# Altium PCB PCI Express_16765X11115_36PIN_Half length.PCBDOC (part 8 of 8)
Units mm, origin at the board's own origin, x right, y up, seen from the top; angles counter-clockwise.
Board outline 178 x 110.97 mm, 10 copper layers (Top Layer, Int1 (GND), Int2 (Sign), Int3 (Sign), Int4 (PWR), Int5 (GND), Int6 (Sign), Int7 (Sign), Int8 (GND), Bottom Layer), stack 1.429 mm thick; 528 components, 525 nets, 2272 pads, 1491 vias.
Unrouted connection lines stored in the file: 373.
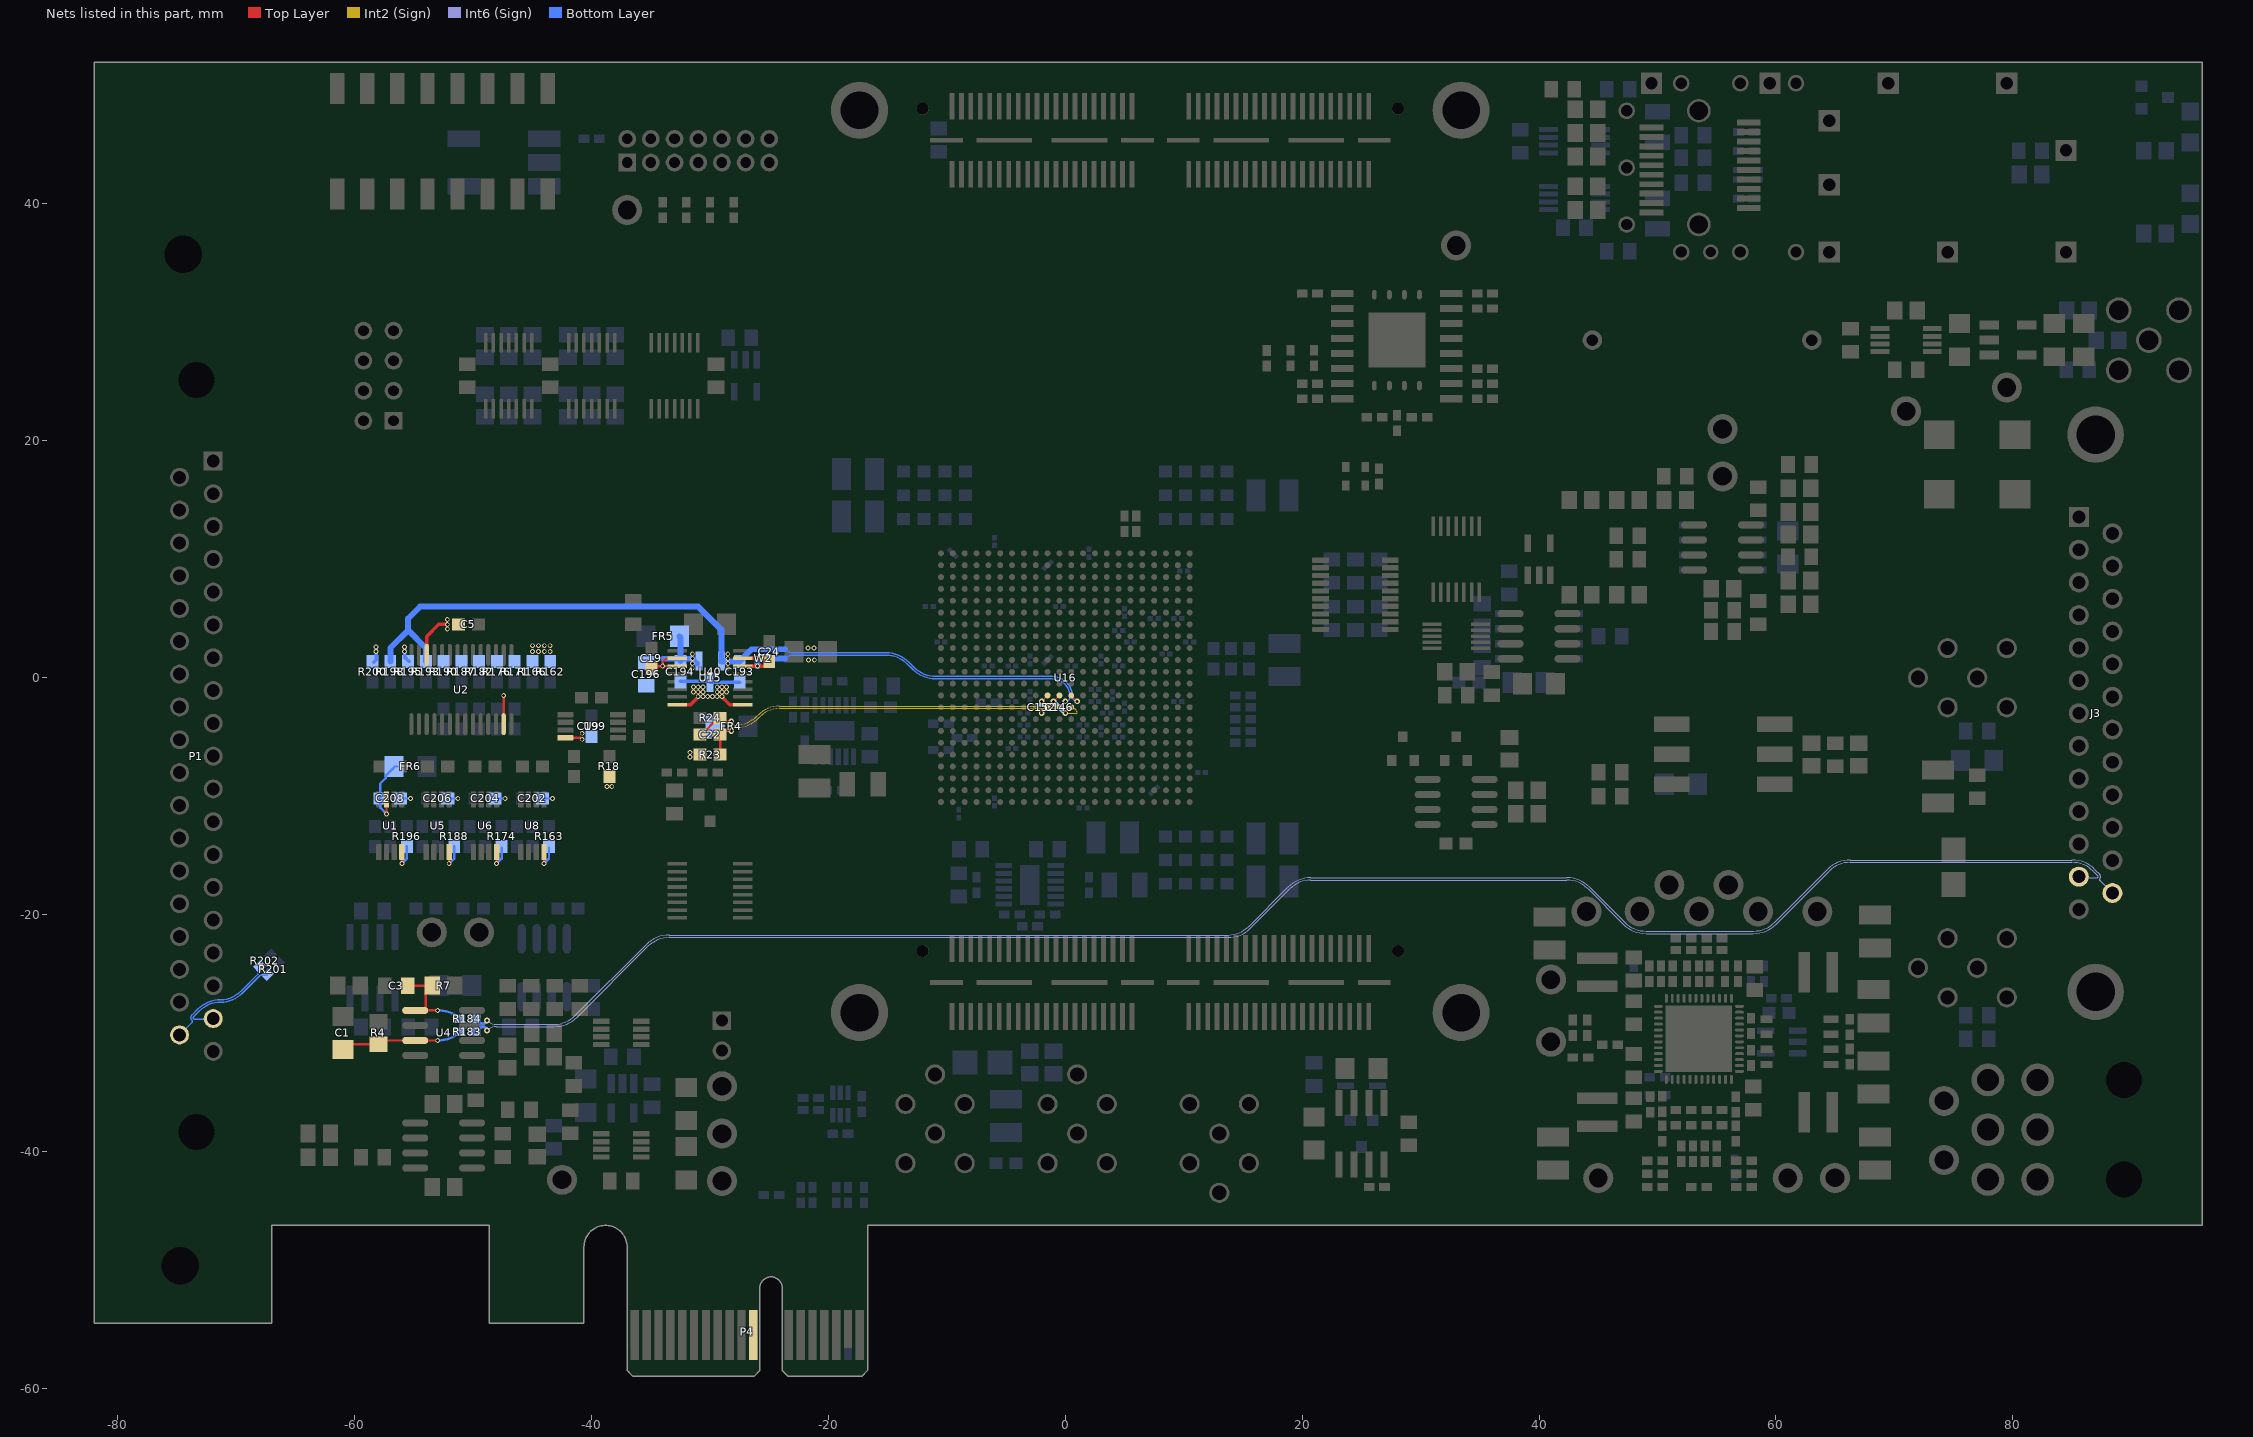
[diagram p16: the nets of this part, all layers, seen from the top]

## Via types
v1: diameter 0.483, hole 0.254, Top Layer to Bottom Layer, tented both sides, 740 vias
v2: diameter 0.508, hole 0.254, Top Layer to Bottom Layer, tented both sides, 302 vias
v3: diameter 0.406, hole 0.254, Top Layer to Bottom Layer, tented both sides, 267 vias
v4: diameter 0.305, hole 0.152, Top Layer to Bottom Layer, tented both sides, 95 vias
v5: diameter 0.5, hole 0.254, Top Layer to Bottom Layer, tented both sides, 50 vias
v6: diameter 0.45, hole 0.254, Top Layer to Bottom Layer, tented both sides, 23 vias
v7: diameter 0.6, hole 0.254, Top Layer to Bottom Layer, tented both sides, 14 vias

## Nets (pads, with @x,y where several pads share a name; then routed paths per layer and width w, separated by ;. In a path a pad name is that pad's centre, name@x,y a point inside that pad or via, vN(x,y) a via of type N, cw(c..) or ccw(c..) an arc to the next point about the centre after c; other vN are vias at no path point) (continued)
VREG2: C208.1 FR6.2 U1.7 | length 6.2
  Top Layer w0.203: v3(-57.325,-11.5) U1.7@-57.325,-10.275
  Bottom Layer w0.203: v3(-57.325,-11.5) -57.85,-10.975 C208.1@-57.85,-10.2 -57.85,-8.95 -57.398,-8.498 -57.398,-8.298 -56.6,-7.5 FR6.2@-56.4,-7.5
WAKE#: P4.B11
X1_N: P1.37 R202.2 | length 9.7
  Bottom Layer w0.127: P1.37@-74.795,-30.17 -73.75,-29.125 ccw(c-73.84,-29.035) -73.713,-29.035 ccw(c-73.84,-29.035) -73.75,-28.945 ; -73.751,-28.944 cw(c-73.519,-28.713) -73.846,-28.713 -73.846,-28.71 cw(c-73.52,-28.71) -73.751,-28.479 -73.271,-28 cw(c-71.333,-29.937) -71.333,-27.197 ccw(c-71.333,-24.8) -69.639,-26.495 -68.17,-25.027 ccw(c-68.322,-24.875) -68.107,-24.875 ccw(c-68.147,-24.875) -68.119,-24.847 cw(c-68.091,-24.819) -68.13,-24.819 -68.13,-24.53 cw(c-67.889,-24.53) R202.2@-68.06,-24.36
X1_P: P1.18 R201.2 | length 9.4
  Bottom Layer w0.127: P1.18@-71.955,-28.785 cw(c-72.084,-28.656) -72.084,-28.839 -73.516,-28.839 cw(c-73.516,-28.712) -73.606,-28.801 cw(c-73.516,-28.712) -73.643,-28.712 cw(c-73.516,-28.712) -73.606,-28.622 -73.128,-28.144 cw(c-71.332,-29.94) -71.332,-27.4 -71.33,-27.4 ccw(c-71.33,-24.808) -69.497,-26.641 -68.027,-25.17 cw(c-67.875,-25.322) -67.875,-25.107 cw(c-67.875,-25.147) -67.847,-25.119 ccw(c-67.819,-25.091) -67.819,-25.13 -67.53,-25.13 ccw(c-67.53,-24.889) R201.2@-67.36,-25.06
XADC.XADC_REF_N: U16.L9 W2.2 | length 28.4
  Top Layer w0.127: U16.L9@-0.5,-2.5 v1(0,-2)
  Bottom Layer w0.127: -23.66,1.63 cw(c-23.009,0.979) -23.009,1.9 -15.139,1.9 cw(c-15.139,-0.64) -13.343,1.156 -12.89,0.703 ccw(c-10.952,2.642) -10.952,-0.1 -10.651,-0.1 ; -10.65,-0.1 -1.103,-0.1 cw(c-1.103,-1.602) 0.398,-1.602 cw(c0,-1.602) v1(0,-2)
  Bottom Layer w0.5: W2.2@-25.162,1.63 -23.66,1.63
XADC.XADC_REF_P: C193.1 R193.2 R198.2 U16.M10 U40.2 | length 71.1
  Top Layer w0.127: U16.M10@0.5,-1.5 v1(1,-2)
  Bottom Layer w0.127: -23.657,2.4 -23.614,2.358 ccw(c-23,2.972) -23,2.103 -15.137,2.103 cw(c-15.137,-0.634) -13.202,1.302 -12.747,0.847 ccw(c-10.951,2.643) -10.951,0.103 -10.651,0.103 -1.103,0.103 cw(c-1.103,-1.602) 0.602,-1.599 cw(c-1.103,-1.602) 0.602,-1.602 ccw(c1,-1.602) v1(1,-2)
  Bottom Layer w0.381: C193.1@-27.5,1.35 C193.1@-27.5,1.4
  Bottom Layer w0.5: R198.2@-57,1.35 -57,2.5 -55.5,4 ; R193.2@-54,1.35 -54,2.5 -55.5,4 ; U40.2@-29.05,1.4 U40.2@-29.05,1.45 ; C193.1@-27.5,1.35 -28.5,1.35 -29.05,1.35 -29.1,1.4 U40.2@-29.05,1.45 ; C193.1@-27.5,1.4 -26.5,2.4 -23.657,2.4 ; -55.5,4 -55.5,5 -54.5,6 -53.3,6 -31,6 -29.05,4.05 U40.2@-29.05,1.45
  other v3: -28.5,0.8 -28.5,1.2 -28.5,1.6 -28.5,2
XADC.XADC_V_N: C22.2 C146.2 R23.2 U16.M9 | length 34.5
  Top Layer w0.127: v1(0,-3) U16.M9@0.5,-2.5
  Top Layer w0.203: R23.2@-29.15,-6.5 C22.2@-29.15,-4.8 -28.85,-4.5 v1(-28.2,-4.5)
  Int2 (Sign) w0.076: v1(-28.2,-4.5) cw(c-27.9,-4.5) -27.9,-4.2 -27.835,-4.2 ccw(c-27.835,-1.46) -25.897,-3.397 -25.8,-3.3 cw(c-24.11,-4.99) -24.11,-2.6 0.6,-2.6 cw(c0.6,-3) 1,-3 v1(0,-3)
XADC.XADC_V_P: C22.1 C146.1 R24.2 U16.L10 | length 32.1
  Top Layer w0.127: v1(-1,-2) U16.L10@-0.5,-1.5
  Top Layer w0.203: C22.1@-30.85,-4.8 -30.452,-4.402 -30.302,-4.402 -29.698,-3.798 -29.548,-3.798 R24.2@-29.15,-3.4 -28.85,-3.7 v1(-28.2,-3.7)
  Int2 (Sign) w0.076: v1(-28.2,-3.7) ccw(c-27.9,-3.7) -27.9,-4 -27.835,-4 ccw(c-27.835,-1.46) -26.039,-3.256 -25.941,-3.159 cw(c-24.11,-4.99) -24.11,-2.4 -1.4,-2.4 ccw(c-1.4,-2) v1(-1,-2)
XADCGND: C5.2 C19.1 C24.1 C152.1 C193.2 C194.2 C196.2 C199.2 C202.2 C204.2 C206.2 C208.2 FR4.2 R18.2 R23.1 R162.2 R163.2 R166.2 R171.2 R174.2 R176.2 R182.2 R187.2 R188.2 R190.2 R195.2 R196.2 R200.2 U1.4 U2.12 U2.27 U5.4 U6.4 U8.4 U9.4 U15.2 U15.3 U15.8 U15.9 U15.14 U15.15 U16.K9 U40.3 W2.1 | length 43.5
  Top Layer w0.127: v1(-2,-3) U16.K9@-1.5,-2.5
  Top Layer w0.203: v3@-56.025,-15.8 U1.4@-56.025,-14.725 ; v3@-52.026,-15.8 v3(-52.025,-15.7) U5.4@-52.025,-14.725 ; v3(-48.025,-15.7) U6.4@-48.025,-14.725 ; U2.27@-47.425,-3.925 v3(-47.425,-1.5) ; U8.4@-44.025,-14.725 -44.022,-14.728 v3(-44.022,-15.7) ; U9.4@-42.225,-5.075 -40.98,-5.075 -40.855,-5.2 v3(-40.8,-5.2) ; C19.1@-34.95,0.775 -34.75,0.975 v3(-34,0.975) ; U15.3@-32.775,0.975 v3(-34,0.975) ; U15.2@-32.775,1.625 -32.806,1.594 -33.743,1.594 -34,1.337 v3(-34,0.975)
  Top Layer w0.3: U2.12@-53.925,1.925 -53.925,3.475 -52.9,4.5 v3@-52.2,4.5 ; U15.8@-32.775,-2.275 -31.65,-2.275 -31,-1.625 v3(-31,-1.6) ; v3(-29,-1.6) -28.325,-2.275 U15.9@-27.225,-2.275 ; U15.14@-27.225,0.975 v3(-26,0.975) -25.35,0.975 C24.1@-25,1.325 ; U15.15@-27.225,1.625 -25.3,1.625 C24.1@-25,1.325 ; C24.1@-25,1.353 C24.1@-25,1.325
  Bottom Layer w0.203: C208.2@-56.1,-10.2 v3(-55.3,-10.2) ; v3(-56.025,-15.7) -55.6,-15.275 R196.2@-55.6,-14.25 ; C206.2@-52.2,-10.2 C206.2@-52.15,-10.2 v3(-51.3,-10.2) ; v3@-52.025,-15.7 -51.6,-15.274 R188.2@-51.6,-14.25 ; C204.2@-48.2,-10.2 C204.2@-48.15,-10.2 v3(-47.3,-10.2) ; v3(-48.025,-15.7) -47.6,-15.275 R174.2@-47.6,-14.35 ; C202.2@-44.2,-10.2 C202.2@-44.15,-10.2 v3(-43.3,-10.2) ; v3(-44.022,-15.7) -43.6,-15.277 R163.2@-43.6,-14.35
  Bottom Layer w0.3: R200.2@-58.4,1.3 -58.2,1.5 v3(-58.2,2.2) v3(-58.2,2.6) ; v3(-55.8,2.6) v3(-55.8,2.2) -55.8,1.75 -55.45,1.4 R195.2@-55.4,1.4 ; C194.2@-32.5,-0.3 -30.1,-0.3 U40.3@-30,-0.4 C193.2@-27.5,-0.4
  Bottom Layer w0.5: v3(-26,0.975) v3(-26,1.625)
  other v3: -38.7,-9.2 -38.3,-9.2 -31.7,-6.7 -31.7,-6.3 -40.8,-4.7 -30.6,-1.6 -30.2,-1.6 -29.8,-1.6 -29.4,-1.6 -31.4,-1.2 -31,-1.2 -30.6,-1.2 -29.4,-1.2 -29,-1.2 -28.6,-1.2 -31.4,-0.8 -31,-0.8 -30.6,-0.8 -29.4,-0.8 -29,-0.8 -28.6,-0.8 -45,2.2 -44.5,2.2 -44,2.2 -43.5,2.2 -21.731,2.5 -21.231,2.5 -45,2.7 -44.5,2.7 -44,2.7 -43.5,2.7 -52.189,4.1 -52.189,4.5 -52.189,4.9
XADCVCC: C152.2 C194.1 C196.1 FR5.2 U16.K10 U40.1 | length 5.9
  Top Layer w0.127: v1(-2,-2) U16.K10@-1.5,-1.5
  Bottom Layer w0.5: -34,1.6 C194.1@-32.5,1.6 ; FR5.2@-32.6,3.5 -32.5,3.4 C194.1@-32.5,1.6 ; C194.1@-32.5,1.4 C194.1@-32.5,1.6 ; U40.1@-31.1,1.2 v3(-31.5,1.6) C194.1@-32.5,1.6
  other v3: -31.5,0.8 -31.5,1.2 -21.7,1.5 -21.2,1.5 -31.5,2
XOCTR_N: C3.2 R7.2 R184.1 U4.5 | length 8.7
  Top Layer w0.203: C3.2@-55.8,-25.9 -55.7,-26 R7.2@-53.45,-26 -53.998,-26.548 -53.998,-27.886 U4.5@-54.21,-28.098 ; U4.5@-54.9,-28.095 -54.898,-28.098 U4.5@-54.21,-28.098 ; v3(-53,-28.1) -53.003,-28.098 U4.5@-54.21,-28.098
  Bottom Layer w0.203: v3(-53,-28.1) -52.84,-28.1 cw(c-52.84,-30.49) R184.1@-51.15,-28.8
XOCTR_P: C1.1 R4.2 R183.1 U4.7 | length 10
  Top Layer w0.203: C1.1@-60.7,-31.5 -60.7,-31.448 -60.202,-30.95 R4.2@-58,-30.95 ; R4.2@-57.9,-30.8 -57.735,-30.635 U4.7@-54.9,-30.635 v3(-53,-30.635)
  Bottom Layer w0.203: v3(-53,-30.635) -52.924,-30.635 ccw(c-52.924,-28.126) R183.1@-51.15,-29.9
XOCTRL_N: J3.25 R184.2 | length 148.7
  Int6 (Sign) w0.076: v2(-48.841,-28.933) ccw(c-48.044,-28.136) -48.044,-29.263 -43.164,-29.263 ccw(c-43.164,-26.723) -41.368,-28.519 -35.385,-22.536 cw(c-33.45,-24.472) -33.45,-21.735 13.713,-21.735 ccw(c13.713,-19.195) 15.509,-20.991 18.8,-17.7 cw(c20.738,-19.637) 20.738,-16.897 42.349,-16.897 cw(c42.349,-19.638) 44.287,-17.7 47.243,-20.656 ccw(c49.039,-18.86) 49.039,-21.4 58.098,-21.4 ccw(c58.098,-18.86) 59.894,-20.656 64.35,-16.2 cw(c66.288,-18.137) 66.288,-15.397 84.999,-15.397 cw(c84.999,-18.138) 86.937,-16.2 87.34,-16.603 cw(c87.145,-16.798) 87.421,-16.798 ; 87.421,-16.8 cw(c87.142,-16.8) 87.339,-16.997 ccw(c87.393,-17.051) 87.317,-17.051 ccw(c87.393,-17.051) 87.339,-17.105 J3.25@88.42,-18.186
  Bottom Layer w0.203: R184.2@-49.85,-28.8 cw(c-49.85,-29.041) -49.679,-28.871 -49.517,-29.033 cw(c-49.553,-29.07) -49.502,-29.07 ccw(c-49.45,-29.07) -49.486,-29.106 ccw(c-49.236,-28.856) -49.236,-29.21 -49.143,-29.21 ccw(c-49.143,-28.95) -48.959,-29.134 -48.941,-29.116 cw(c-48.8,-29.257) -48.8,-29.058 v2(-48.841,-28.933)
XOCTRL_P: J3.12 R183.2 | length 148.2
  Int6 (Sign) w0.076: v2(-48.841,-29.797) cw(c-48.044,-30.594) -48.044,-29.467 -43.163,-29.467 ccw(c-43.163,-26.726) -41.225,-28.664 -35.243,-22.682 cw(c-33.447,-24.478) -33.447,-21.938 13.714,-21.938 ccw(c13.714,-19.197) 15.652,-21.135 18.943,-17.844 cw(c20.739,-19.64) 20.739,-17.1 42.348,-17.1 cw(c42.348,-19.64) 44.144,-17.844 47.1,-20.8 ccw(c49.039,-18.861) 49.039,-21.603 58.099,-21.603 ccw(c58.099,-18.863) 60.037,-20.8 64.493,-16.344 cw(c66.289,-18.14) 66.289,-15.6 84.998,-15.6 cw(c84.998,-18.14) 86.794,-16.344 87.196,-16.746 cw(c87.142,-16.8) 87.218,-16.8 cw(c87.142,-16.8) 87.196,-16.854 cw(c87.142,-16.8) 87.142,-16.876 85.751,-16.876 cw(c85.751,-16.634) J3.12@85.58,-16.805
  Bottom Layer w0.203: R183.2@-49.85,-29.9 ccw(c-49.85,-29.659) -49.679,-29.829 -49.517,-29.667 ccw(c-49.553,-29.63) -49.502,-29.63 cw(c-49.45,-29.63) -49.486,-29.594 cw(c-49.236,-29.844) -49.236,-29.49 -49.143,-29.49 cw(c-49.143,-29.75) -48.959,-29.566 -48.941,-29.584 ccw(c-48.8,-29.443) -48.8,-29.642 v2(-48.841,-29.797)
pads on no net: J1.7 J1.23 J1.24 J2.MH1 J2.MH2 J3.26 J3.27 P1.S1 P1.S2 P3.12 P3.14 P4.B12 P5.1 P5.2 P5.3 P5.4 P5.89 P5.90 P6.89 P6.90 S2.2 S2.4 U2.2 U2.3 U2.13 U3.1 U3.5 U3.8 U16.A6 U16.AA9 U16.AA10 U16.AA11 U16.AA13 U16.AA14 U16.AA15 U16.AA16 U16.AB10 U16.AB11 U16.AB12 U16.AB13 U16.AB15 U16.AB16 U16.AB17 U16.B6 U16.C5 U16.C7 U16.D5 U16.D7 U16.E10 U16.F10 U16.T14 U16.T15 U16.T16 U16.U15 U16.U16 U16.V10 U16.V13 U16.V14 U16.V15 U16.W10 U16.W11 U16.W12 U16.W14 U16.W15 U16.W16 U16.Y11 U16.Y12 U16.Y13 U16.Y14 U16.Y16 U16.Y17 U18.4 U18.5 U18.6 U18.11 U18.12 U18.13 U18.14 U19.1 U19.6 U20.9 U23.6 U23.8 U27.2 U29.1 U31.1 U31.3 U31.5 U31.7 U31.8 U32.1 U33.1 U33.4 U42.1 U42.3 U42.5 U42.7 U42.8
copper on no net:
  other v3: -40.2,-9.2 -39.8,-9.2
  other v5: 26,26.5 27,26.5 28,26.5 29,26.5 30,26.5 26,27.5 27,27.5 28,27.5 29,27.5 30,27.5 26,28.5 27,28.5 28,28.5 29,28.5 30,28.5 26,29.5 27,29.5 28,29.5 29,29.5 30,29.5 26,30.5 27,30.5 28,30.5 29,30.5 30,30.5

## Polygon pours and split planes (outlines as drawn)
P12V on Int3 (Sign) "P12V_L04_P049" (solid, pour order 49): -61.5,-41.8 -61.5,-19 -41.857,-19 -32.357,-28.5 7,-28.5 7,-43.2 -37.585,-43.154 -42.6,-43.2 -44.2,-41.8
SFP_SH on Int3 (Sign) "S0" (solid, pour order 8): 95.5,34.5 46.5,34.5 46.5,51.5 95.5,51.5
no net on Int3 (Sign) "SHLD" (solid, pour order 4): -82,52 -77.5,52 -77.5,-54.5 -82,-54.5
NetC61_2 on Top Layer "NETC61_2_L01_P024" (solid, pour order 24): 63.375,-30.428 58.45,-30.428 58.45,-29.375 57.5,-29.375 57.5,-28.625 57.5,-28.3 59.375,-28.3 59.375,-22.248 63.375,-22.248
no net on Top Layer "NONET_L01_P083" (solid, pour order 83): -26.2,-5
GND on Top Layer "SW_GND" (solid, pour order 13): 66.8,-29.5 63.925,-29.5 63.925,-30.75 66.8,-30.75 66.8,-32 63.925,-32 63.925,-33.3 70.05,-33.3 70.05,-28.2 66.8,-28.2
NetC60_2 on Top Layer "SW_PWR_2" (solid, pour order 22): 63.2,-39.25 59.5,-39.25 59.5,-33.25 57.552,-33.25 57.552,-32.125 58.5,-32.125 58.5,-31.05 63.2,-31.05
GND on Top Layer "GND_L01_P077" (solid, pour order 77): 49.5,9 50,9.5 50,12.5 49.5,13 47.9,13 47.9,9
VCC on Top Layer "VCC_L01_P071" (solid, pour order 71): 38.702,12.103 38.702,10.048 ccw(c39.05,10.048) 39.05,9.7 40,9.7 ccw(c40,10) 40.3,10 40.3,11.8 ccw(c40,11.8) 40,12.1 38.7,12.1
no net on Top Layer "NONET_L01_P064" (solid, pour order 64): 57.6,12.6
no net on Top Layer "NONET_L01_P063" (solid, pour order 63): 57.4,12.6
P10V on Top Layer "P10V_L01_P055" (solid, pour order 55): 40.5,1.9 40.5,1.2 38.9,1.2 38.3,0.6 35.3,0.6 35.3,1.5 35.9,1.5 36.3,1.9
no net on Top Layer "NONET_L01_P056" (solid, pour order 56): 37.2,0
XADCVCC on Bottom Layer "XADCVCC_L10_P090" (solid, pour order 90): -2.4,-1.9 -2.4,-1.3 ccw(c-2.9,-1.3) -2.9,-0.8 -10.993,-0.8 cw(c-10.993,3.08) -13.736,0.336 ccw(c-15.58,-1.507) -15.58,1.1 -22.1,1.1 cw(c-22.1,1.5) -22.5,1.506 ccw(c-35.131,1.702) -22.5,1.9 -22.44,1.9 -15.066,1.9 cw(c-15.065,-0.431) -13.417,1.217 -12.895,0.695 ccw(c-10.976,2.614) -10.976,-0.1 -1.183,-0.1 cw(c-1.183,-1.748) -0.017,-0.583 cw(c-1.024,-1.59) 0.4,-1.59 0.4,-1.9 cw(c0,-1.9) 0,-2.3 -2,-2.3 cw(c-2,-1.9)
XADCGND on Bottom Layer "XADCGND_L10_P087" (solid, pour order 87): -2.8,-3.1 -2.8,-4.3 ccw(c-2.4,-4.3) -2.4,-4.7 -0.041,-4.7 ccw(c-0.041,-3.875) 0.543,-4.458 1.589,-3.41 ccw(c0.594,-2.417) 2,-2.417 2,0.1 ccw(c1.498,0.1) 1.498,0.602 -9.702,0.602 -10.529,0.602 cw(c-10.529,2.723) -12.222,1.445 ccw(c-15.058,-0.693) -13.712,2.594 ccw(c-15.268,-1.185) -15.273,2.902 -22.098,2.902 ccw(c-22.099,2.5) -22.5,2.5 -22.5,2.032 -14.868,2.035 cw(c-14.866,-0.213) -13.277,1.377 -12.683,0.784 ccw(c-11.032,2.436) -11.032,0.1 -1.099,0.1 cw(c-1.098,-1.598) 0.599,-1.598 0.599,-1.901 cw(c-0.198,-1.901) -0.198,-2.698 -2.398,-2.698 ccw(c-2.398,-3.1)
no net on Bottom Layer "NONET_L10_P086" (solid, pour order 86): -0.5,-1.5
no net on Bottom Layer "NONET_L10_P085" (solid, pour order 85): -24,3
GND on Bottom Layer "GND_L10_P084" (solid, pour order 84): 21.8,10.6 25,13.8 30.5,13.8 30.5,9 28,9 28,10.3 21.8,10.3
GND on Bottom Layer "GND_L10_P082" (solid, pour order 82): 7.9,17.5 7.9,17.9 9,19 9.2,19 9.2,17.5
no net on Bottom Layer "NONET_L10_P081" (solid, pour order 81): -10.7,19.2
no net on Bottom Layer "NONET_L10_P080" (solid, pour order 80): -20.5,14.8
AGND on Bottom Layer "AGND_L10_P076" (solid, pour order 76): 57,9.4 55.9,8.3 55.9,6.9 58.8,4 60.5,4 61.9,5.4 61.9,10.4 60.1,10.4 59.1,9.4
AGND on Bottom Layer "AGND_L10_P074" (solid, pour order 74): 45.6,4.2 45.4,4.4 43.5,4.4 43.5,2.6 45.4,2.6 45.6,2.8
P10V on Bottom Layer "P10V_L10_P073" (solid, pour order 73): 39.5,15 39.24,15 ccw(c39.24,12.46) 36.7,12.46 36.7,8.4 38.3,8.4 38.3,12.3 cw(c39.5,12.3) 39.5,13.5
P10V on Bottom Layer "P10V_L10_P068" (solid, pour order 68): 56.5,15 ccw(c56.5,14.5) 56,14.5 56,11.8 ccw(c56.5,11.8) 56.5,11.3 61.5,11.3 ccw(c61.5,11.8) 62,11.8 62,14.5 ccw(c61.5,14.5) 61.5,15
no net on Bottom Layer "NONET_L10_P067" (solid, pour order 67): 56.5,15
AGND on Bottom Layer "AGND_L10_P062" (solid, pour order 62): 32.7,4 ccw(c33,4) 33,3.7 33.5,3.7 ccw(c33.5,4) 33.8,4 33.8,5.2 cw(c34.2,5.2) 34.2,5.6 36,5.6 36,6.9 34.4,6.9 ccw(c34.4,5.2) 32.7,5.2
AGND on Bottom Layer "AGND_L10_P057" (solid, pour order 57): 41.3,0.5 41.3,-1.3 39.9,-2.7 37.3,-2.7 37.3,-1.6 39.4,-1.6 39.7,-1.3 39.7,0.5
P10V on Bottom Layer "NONET_L10_P054" (solid, pour order 54): 38.5,-1.3 38.5,0.796 38.904,1.2 40.5,1.2 40.5,1.899 36.299,1.899 35.9,1.5 34.4,1.5 34.4,-0.9 34.8,-1.3
GND on Bottom Layer "GND_L10_P053" (solid, pour order 53): -22.3,-3.2 -22.3,-3.7 -23.4,-4.8 -23.4,-5.8 -21.5,-5.8 -20.5,-4.8 -20.5,-3.7 -21.3,-3.7 -21.8,-3.2
no net on Bottom Layer "NONET_L10_P047" (solid, pour order 47): -41.2,-39.2
no net on Bottom Layer "NONET_L10_P046" (solid, pour order 46): -39.6,-33.1
no net on Bottom Layer "NONET_L10_P045" (solid, pour order 45): -42,-29.8
NetC128_2 on Bottom Layer "NETC88_2" (solid, pour order 44): 4.5,-19 4.5,-16 3.5,-15 3.5,-12 1.648,-12 1.648,-17.3 2.3,-17.3 2.7,-17.7 2.7,-19
no net on Bottom Overlay "NONET_L-01_P-001" (solid): -37.9,-39.5
AVCC1V8 on Int7 (Sign) "AVCC1V8_L08_P079" (solid, pour order 79): 42.5,-30.6 42.5,-35.2 -7.1,-35.2 -38.8,-3.5 -38.8,4.5 -34.5,4.5 -34.5,-1.7 -5.6,-30.6
no net on Int7 (Sign) "NONET_L08_P078" (solid, pour order 78): 43,-29
P5V on Int7 (Sign) "P5V_L08_P052" (solid, pour order 52): -66.748,-45.743 -66.748,-25.604 -60.296,-19.152 -41.704,-19.152 -34.252,-26.604 -34.252,-43.389 -36.606,-45.743 -40.849,-45.743 -48.455,-45.743
N12V on Int2 (Sign) "N12V_L03_P048" (solid, pour order 48): 12.198,-43.2 12.198,-28.52 -32.38,-28.52 -41.9,-19 -61.5,-19 -61.5,-41.8 -44.2,-41.8 -42.8,-43.2 -31.3,-43.2
GND on Int1 (GND) (split plane): 159 vertices, not listed, extent -81.49,-58.49 79.248,51.458
VREF2V5 on Int1 (GND) (split plane): -38.252,-43.748 -54.748,-43.748 -54.748,-25.252 -38.252,-25.252
VCC2 on Int1 (GND) (split plane): -33.252,5.396 -33.252,4.104 -36.178,1.178 -36.218,1.126 -36.244,1.065 -36.252,1 -36.252,0 -36.252,-6.5 -36.252,-9.396 -39.104,-12.248 -40,-12.248 -57.896,-12.248 -60.648,-9.496 -60.648,1.496 -55.896,6.248 -34.104,6.248
EXT12V on Int1 (GND) (split plane): 83.748,-33.104 83.748,-42.5 83.748,-42.896 82.796,-43.848 80.154,-43.848 72.752,-36.446 72.752,-27.104 74.104,-25.752 76.396,-25.752
12V on Int1 (GND) (split plane): 95.49,-45.74 -4.748,-45.74 -4.748,-36.604 -3.322,-35.178 -1.896,-33.752 39.5,-33.752 39.565,-33.744 39.626,-33.718 39.678,-33.678 39.718,-33.626 39.744,-33.565 39.752,-33.5 39.752,-25 39.745,-24.943 39.744,-24.935 39.733,-24.91 39.718,-24.874 39.709,-24.862 39.678,-24.822 32.678,-17.822 29.252,-14.396 29.252,-12.104 30.604,-10.752 64,-10.752 64.065,-10.744 64.126,-10.718 64.178,-10.678 67.678,-7.178 68.178,-6.678 79.678,4.822 79.696,4.844 79.718,4.874 79.744,4.935 79.752,5 79.752,6.5 79.752,24.6 79.744,24.665 79.718,24.726 79.678,24.778 61.778,42.678 61.726,42.718 61.665,42.744 61.6,42.752 24.604,42.752 20.252,47.104 20.252,51.458 95.49,51.458
XADCVCC on Int1 (GND) (split plane): -20.752,0.252 -35.748,0.252 -35.748,0.896 -32.896,3.748 -20.752,3.748
VCC1V8 on Int1 (GND) (split plane): 19.748,-2 19.748,-3.396 6.396,-16.748 4.604,-16.748 0.752,-12.896 0.752,-1.5 0.744,-1.435 0.718,-1.374 0.678,-1.322 0.626,-1.282 0.565,-1.256 0.5,-1.248 -11,-1.248 -11.065,-1.256 -11.126,-1.282 -11.178,-1.322 -13.678,-3.822 -13.718,-3.874 -13.744,-3.935 -13.752,-4 -13.752,-8.896 -14.604,-9.748 -16.748,-9.748 -16.748,-1.604 -12.896,2.248 19.748,2.248
VCC on Int4 (PWR) (split plane): 95.49,-45.74 -16.7,-45.74 -16.8,-45.749 -16.895,-45.778 -16.984,-45.826 -17.061,-45.889 -17.124,-45.966 -17.172,-46.055 -17.201,-46.15 -17.21,-46.25 -17.21,-58.289 -17.411,-58.49 -23.189,-58.49 -23.39,-58.289 -23.39,-51.55 -23.39,-51.546 -23.399,-51.386 -23.426,-51.225 -23.472,-51.068 -23.534,-50.916 -23.614,-50.773 -23.708,-50.64 -23.817,-50.517 -23.94,-50.408 -24.073,-50.314 -24.216,-50.234 -24.368,-50.172 -24.525,-50.126 -24.686,-50.099 -24.85,-50.09 -25.014,-50.099 -25.175,-50.126 -25.332,-50.172 -25.484,-50.234 -25.627,-50.314 -25.76,-50.408 -25.883,-50.517 -25.992,-50.64 -26.086,-50.773 -26.166,-50.916 -26.228,-51.068 -26.274,-51.225 -26.301,-51.386 -26.31,-51.546 -26.31,-51.55 -26.31,-58.289 -26.511,-58.49 -36.289,-58.49 -36.49,-58.289 -36.49,-48.075 -36.49,-48.071 -36.499,-47.871 -36.525,-47.669 -36.569,-47.471 -36.631,-47.276 -36.709,-47.088 -36.803,-46.907 -36.912,-46.736 -37.036,-46.574 -37.174,-46.424 -37.324,-46.286 -37.486,-46.162 -37.657,-46.053 -37.838,-45.959 -38.026,-45.881 -38.221,-45.819 -38.419,-45.775 -38.621,-45.749 -38.825,-45.74 -39.029,-45.749 -39.231,-45.775 -39.429,-45.819 -39.624,-45.881 -39.812,-45.959 -39.993,-46.053 -40.164,-46.162 -40.326,-46.286 -40.476,-46.424 -40.614,-46.574 -40.738,-46.736 -40.847,-46.907 -40.941,-47.088 -41.019,-47.276 -41.081,-47.471 -41.125,-47.669 -41.151,-47.871 -41.16,-48.071 -41.16,-48.075 -41.16,-53.99 -48.14,-53.99 -48.14,-46.25 -48.149,-46.15 -48.178,-46.055 -48.226,-45.966 -48.289,-45.889 -48.366,-45.826 -48.455,-45.778 -48.55,-45.749 -48.65,-45.74 -67,-45.74 -67.1,-45.749 -67.195,-45.778 -67.284,-45.826 -67.361,-45.889 -67.424,-45.966 -67.472,-46.055 -67.501,-46.15 -67.51,-46.25 -67.51,-53.99 -81.49,-53.99 -81.49,51.458 95.49,51.458
AVTT on Int4 (PWR) (split plane): -9.752,-3.5 -9.744,-3.565 -9.718,-3.626 -9.678,-3.678 -9.626,-3.718 -9.565,-3.744 -9.5,-3.752 -8.752,-3.752 -8.752,-8.5 -8.752,-20.748 -24.748,-20.748 -24.748,-0.752 -9.752,-0.752
AVCC on Int4 (PWR) (split plane): -4.752,1 -4.752,-0.5 -4.752,-4.5 -4.752,-5.5 -4.752,-6.5 -4.752,-20.748 -8.248,-20.748 -8.248,-8.5 -8.248,-3.5 -8.256,-3.435 -8.282,-3.374 -8.322,-3.322 -8.374,-3.282 -8.435,-3.256 -8.5,-3.248 -9.248,-3.248 -9.248,-0.5 -9.256,-0.435 -9.282,-0.374 -9.322,-0.322 -9.374,-0.282 -9.435,-0.256 -9.5,-0.248 -24.748,-0.248 -24.748,13.248 -4.752,13.248
VCCINT on Int4 (PWR) (split plane): 2.248,-1.5 2.256,-1.565 2.282,-1.626 2.322,-1.678 2.374,-1.718 2.435,-1.744 2.5,-1.752 16.896,-1.752 20.322,-5.178 34.748,-19.604 34.748,-21.3 34.756,-21.365 34.782,-21.426 34.822,-21.478 40.322,-26.978 40.374,-27.018 40.435,-27.044 40.5,-27.052 51.696,-27.052 65.622,-40.978 66.348,-41.704 66.348,-42.796 65.822,-43.322 65.596,-43.548 64.404,-43.548 60.851,-39.995 60.844,-39.935 60.818,-39.874 60.778,-39.822 60.726,-39.782 60.665,-39.756 60.605,-39.749 50.678,-29.822 50.626,-29.782 50.565,-29.756 50.5,-29.748 38.104,-29.748 29.178,-20.822 29.126,-20.782 29.065,-20.756 29,-20.748 -4.248,-20.748 -4.248,-5.5 -4.248,-4.5 -4.248,-0.752 2.248,-0.752
P10V on Int4 (PWR) (split plane): 38.248,10.096 38.248,4 38.256,3.935 38.282,3.874 38.322,3.822 40.448,1.696 40.448,1.504 39.596,0.652 37.004,0.652 36.752,0.904 36.752,10.096 37.004,10.348 37.996,10.348
VCC1V8 on Int4 (PWR) (split plane): 24.822,-0.178 34.422,-9.778 42.548,-17.904 42.548,-26.548 40.604,-26.548 35.252,-21.196 35.252,-19.5 35.244,-19.435 35.218,-19.374 35.178,-19.322 20.678,-4.822 17.178,-1.322 17.126,-1.282 17.065,-1.256 17,-1.248 2.752,-1.248 2.752,-0.5 2.744,-0.435 2.718,-0.374 2.678,-0.322 2.626,-0.282 2.565,-0.256 2.5,-0.248 -4.248,-0.248 -4.248,13.248 11.396,13.248
GND on Int5 (GND) (split plane): 95.49,-45.74 -16.7,-45.74 -16.8,-45.749 -16.895,-45.778 -16.984,-45.826 -17.061,-45.889 -17.124,-45.966 -17.172,-46.055 -17.201,-46.15 -17.21,-46.25 -17.21,-58.289 -17.411,-58.49 -23.189,-58.49 -23.39,-58.289 -23.39,-51.55 -23.39,-51.546 -23.399,-51.386 -23.426,-51.225 -23.472,-51.068 -23.534,-50.916 -23.614,-50.773 -23.708,-50.64 -23.817,-50.517 -23.94,-50.408 -24.073,-50.314 -24.216,-50.234 -24.368,-50.172 -24.525,-50.126 -24.686,-50.099 -24.85,-50.09 -25.014,-50.099 -25.175,-50.126 -25.332,-50.172 -25.484,-50.234 -25.627,-50.314 -25.76,-50.408 -25.883,-50.517 -25.992,-50.64 -26.086,-50.773 -26.166,-50.916 -26.228,-51.068 -26.274,-51.225 -26.301,-51.386 -26.31,-51.546 -26.31,-51.55 -26.31,-58.289 -26.511,-58.49 -36.289,-58.49 -36.49,-58.289 -36.49,-48.075 -36.49,-48.071 -36.499,-47.871 -36.525,-47.669 -36.569,-47.471 -36.631,-47.276 -36.709,-47.088 -36.803,-46.907 -36.912,-46.736 -37.036,-46.574 -37.174,-46.424 -37.324,-46.286 -37.486,-46.162 -37.657,-46.053 -37.838,-45.959 -38.026,-45.881 -38.221,-45.819 -38.419,-45.775 -38.621,-45.749 -38.825,-45.74 -39.029,-45.749 -39.231,-45.775 -39.429,-45.819 -39.624,-45.881 -39.812,-45.959 -39.993,-46.053 -40.164,-46.162 -40.326,-46.286 -40.476,-46.424 -40.614,-46.574 -40.738,-46.736 -40.847,-46.907 -40.941,-47.088 -41.019,-47.276 -41.081,-47.471 -41.125,-47.669 -41.151,-47.871 -41.16,-48.071 -41.16,-48.075 -41.16,-53.99 -48.14,-53.99 -48.14,-46.25 -48.149,-46.15 -48.178,-46.055 -48.226,-45.966 -48.289,-45.889 -48.366,-45.826 -48.455,-45.778 -48.55,-45.749 -48.65,-45.74 -67,-45.74 -67.1,-45.749 -67.195,-45.778 -67.284,-45.826 -67.361,-45.889 -67.424,-45.966 -67.472,-46.055 -67.501,-46.15 -67.51,-46.25 -67.51,-53.99 -81.49,-53.99 -81.49,51.458 95.49,51.458
BGND on Int5 (GND) (split plane): -30.878,-29.978 -30.278,-30.578 -30.226,-30.618 -30.165,-30.644 -30.1,-30.652 0.296,-30.652 2.248,-32.604 2.248,-33.074 2.248,-33.2 2.248,-36.6 2.248,-38 2.256,-38.065 2.282,-38.126 2.322,-38.178 3.322,-39.178 3.344,-39.196 3.374,-39.218 3.435,-39.244 3.5,-39.252 5.2,-39.252 5.265,-39.244 5.326,-39.218 5.378,-39.178 9.604,-34.952 11.196,-34.952 14.048,-37.804 14.048,-43.848 11.952,-43.848 11.952,-39.7 11.952,-39.3 11.944,-39.235 11.918,-39.174 11.878,-39.122 11.078,-38.322 11.026,-38.282 10.965,-38.256 10.9,-38.248 9.4,-38.248 9.335,-38.256 9.274,-38.282 9.222,-38.322 5.296,-42.248 4,-42.248 3.95,-42.254 3.9,-42.248 3.004,-42.248 -0.248,-38.996 -0.248,-34 -0.256,-33.935 -0.282,-33.874 -0.304,-33.844 -0.322,-33.822 -1.522,-32.622 -1.574,-32.582 -1.635,-32.556 -1.7,-32.548 -29.5,-32.548 -29.565,-32.556 -29.626,-32.582 -29.678,-32.622 -30.678,-33.622 -30.718,-33.674 -30.744,-33.735 -30.752,-33.8 -30.752,-35.2 -30.744,-35.265 -30.718,-35.326 -30.678,-35.378 -29.678,-36.378 -29.656,-36.396 -29.626,-36.418 -29.565,-36.444 -29.5,-36.452 -27.704,-36.452 -26.752,-37.404 -26.752,-39.796 -27.704,-40.748 -29.6,-40.748 -29.665,-40.756 -29.726,-40.782 -29.778,-40.822 -30.678,-41.722 -30.718,-41.774 -30.744,-41.835 -30.752,-41.9 -30.752,-42.596 -31.304,-43.148 -42.796,-43.148 -44.122,-41.822 -44.174,-41.782 -44.235,-41.756 -44.3,-41.748 -61.448,-41.748 -61.448,-24.9 -61.448,-19.052 -41.804,-19.052
XADCGND on Int5 (GND) (split plane): -29.978,5.322 -27.678,3.022 -27.656,3.004 -27.626,2.982 -27.565,2.956 -27.5,2.948 -20.852,2.948 -20.852,1.052 -23.1,1.052 -23.165,1.044 -23.226,1.018 -23.278,0.978 -23.318,0.926 -23.344,0.865 -23.352,0.8 -23.352,-3.096 -23.904,-3.648 -26.3,-3.648 -26.365,-3.656 -26.426,-3.682 -26.478,-3.722 -28.004,-5.248 -29.5,-5.248 -29.565,-5.256 -29.626,-5.282 -29.678,-5.322 -40.204,-15.848 -58.296,-15.848 -60.648,-13.496 -60.648,1.496 -55.896,6.248 -30.904,6.248
AGND on Int5 (GND) (split plane): 80.748,14.396 80.748,3 80.748,1.604 78.322,-0.822 63.896,-15.248 46.104,-15.248 42.752,-11.896 42.752,-7 42.744,-6.935 42.718,-6.874 42.696,-6.844 42.678,-6.822 39.678,-3.822 39.626,-3.782 39.565,-3.756 39.5,-3.748 33.604,-3.748 32.252,-2.396 32.252,5.396 34.604,7.748 48.5,7.748 48.565,7.756 48.626,7.782 48.678,7.822 50.678,9.822 50.701,9.851 50.718,9.874 50.726,9.892 50.744,9.935 50.752,10 50.752,16.896 53.604,19.748 75.396,19.748
VDD on Int8 (GND) (split plane): 95.49,-45.74 -16.7,-45.74 -16.8,-45.749 -16.895,-45.778 -16.984,-45.826 -17.061,-45.889 -17.124,-45.966 -17.172,-46.055 -17.201,-46.15 -17.21,-46.25 -17.21,-58.289 -17.411,-58.49 -23.189,-58.49 -23.39,-58.289 -23.39,-51.55 -23.39,-51.546 -23.399,-51.386 -23.426,-51.225 -23.472,-51.068 -23.534,-50.916 -23.614,-50.773 -23.708,-50.64 -23.817,-50.517 -23.94,-50.408 -24.073,-50.314 -24.216,-50.234 -24.368,-50.172 -24.525,-50.126 -24.686,-50.099 -24.85,-50.09 -25.014,-50.099 -25.175,-50.126 -25.332,-50.172 -25.484,-50.234 -25.627,-50.314 -25.76,-50.408 -25.883,-50.517 -25.992,-50.64 -26.086,-50.773 -26.166,-50.916 -26.228,-51.068 -26.274,-51.225 -26.301,-51.386 -26.31,-51.546 -26.31,-51.55 -26.31,-58.289 -26.511,-58.49 -36.289,-58.49 -36.49,-58.289 -36.49,-48.075 -36.49,-48.071 -36.499,-47.871 -36.525,-47.669 -36.569,-47.471 -36.631,-47.276 -36.709,-47.088 -36.803,-46.907 -36.912,-46.736 -37.036,-46.574 -37.174,-46.424 -37.324,-46.286 -37.371,-46.25 -36.505,-46.25 -36.439,-46.241 -36.378,-46.216 -36.326,-46.176 -33.822,-43.672 -33.782,-43.619 -33.756,-43.559 -33.748,-43.493 -33.748,-26.5 -33.756,-26.435 -33.782,-26.374 -33.822,-26.322 -41.422,-18.722 -41.474,-18.682 -41.535,-18.656 -41.6,-18.648 -60.4,-18.648 -60.465,-18.656 -60.526,-18.682 -60.578,-18.722 -67.178,-25.322 -67.218,-25.374 -67.244,-25.435 -67.252,-25.5 -67.252,-45.809 -67.284,-45.826 -67.361,-45.889 -67.424,-45.966 -67.472,-46.055 -67.501,-46.15 -67.51,-46.25 -67.51,-53.99 -81.49,-53.99 -81.49,51.458 95.49,51.458
no net on Int8 (GND) (split plane): -40.326,-46.286 -40.476,-46.424 -40.614,-46.574 -40.738,-46.736 -40.847,-46.907 -40.941,-47.088 -41.019,-47.276 -41.081,-47.471 -41.125,-47.669 -41.151,-47.871 -41.16,-48.071 -41.16,-48.075 -41.16,-53.99 -48.14,-53.99 -48.14,-46.255 -40.286,-46.255
N5V on Int8 (GND) (split plane): -34.252,-26.604 -34.252,-43.389 -36.609,-45.746 -38.648,-45.746 -38.658,-45.747 -38.825,-45.74 -39.029,-45.749 -39.047,-45.751 -48.545,-45.751 -48.55,-45.749 -48.65,-45.74 -66.748,-45.74 -66.748,-25.604 -60.296,-19.152 -41.704,-19.152

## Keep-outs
Top Layer:
  rectangle: -82,30.7 -69.3,51.15
  rectangle: -16.7,-46.25 96,-45.25
  region: -82,-54.55 -67,-54.55 ccw(c-67,-54.5) -66.95,-54.5 -66.95,-46.3 -48.7,-46.3 -48.7,-51.05 ccw(c-48.65,-51.05) -48.65,-51.1 -40.65,-51.1 ccw(c-40.65,-51.05) -40.6,-51.05 ccw(c-40.65,-51.05) -40.6,-51.049 -40.6,-48.075 cw(c-38.825,-48.075) -37.05,-48.075 ccw(c-37,-48.075) -36.95,-48.075 -36.95,-45.25 ccw(c-37,-45.25) -37,-45.2 -82,-45.2 ccw(c-82,-45.25) -82.05,-45.25 -82.05,-54.5 ccw(c-82,-54.5)
Bottom Layer:
  rectangle: -16.7,-46.25 85.65,-45.25
  rectangle: -82,30.7 -69.3,51.15
  region: -82,-54.55 -67,-54.55 ccw(c-67,-54.5) -66.95,-54.5 -66.95,-46.3 -48.7,-46.3 -48.7,-51.05 ccw(c-48.65,-51.05) -48.65,-51.1 -40.65,-51.1 ccw(c-40.65,-51.05) -40.6,-51.05 ccw(c-40.65,-51.05) -40.6,-51.049 -40.6,-48.075 cw(c-38.825,-48.075) -37.05,-48.075 ccw(c-37,-48.075) -36.95,-48.075 -36.95,-45.25 ccw(c-37,-45.25) -37,-45.2 -82,-45.2 ccw(c-82,-45.25) -82.05,-45.25 -82.05,-54.5 ccw(c-82,-54.5)
Top Solder:
  rectangle: -48.65,-54.5 -40.65,-51.05
Bottom Solder:
  rectangle: -48.65,-54.5 -40.65,-51.05
KeepOutLayer:
  rectangle: -48.65,-54.5 -40.65,-51.05

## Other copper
Top Layer:
  rectangle net VDD: -20.9,0.5 -19.9,1.5
  rectangle net GND: 57,-24.8 57.7,-23.3
  rectangle net AVCC1V8: 39.8,-30.75 42.2,-29.187
  rectangle net AVCC1V8: 39.8,-29.375 42.634,-28.45
  rectangle net GND: 52.8,-24.7 54.1,-23
  rectangle net GND: 50.1,-24.7 50.5,-23.2
  rectangle net VDD: 46.125,-31.9 46.75,-30.625
  rectangle net GND: 56.3,-39.55 57.4,-38.65
  rectangle net 12V: 46.937,-32.437 48.712,-31.812
  rectangle net GND: 43.7,-32.437 45.812,-29.75
  rectangle net AVCC1V8: 42.062,-29.375 44.5,-28.45
  rectangle net GND: 52.4,-36.9 54.6,-36.1
  rectangle net GND: 49.6,-39.55 50.8,-38.65
  rectangle net GND: 47.232,-34.85 48.732,-33
  rectangle net 12V: 46.812,-29.85 48.687,-28.687
  rectangle net GND: 47.3,-26.725 48.7,-25.05
  rectangle net GND: 57.4,-37.45 58.8,-35.95
  rectangle net 12V: 57.4,-35.05 58.8,-33.45
  rectangle net 12V: 57.5,-27.4 58.9,-25.625
  rectangle net VCC: 39.8,-44.3 46.6,-40.4
  rectangle net GND: 47.232,-36.225 48.732,-34.375
  rectangle net GND: 47.3,-27.85 48.7,-26.183
  rectangle net SENSE.SENS_10_P: 63.9,-40.1 70,-33.7
  rectangle net VCCINT: 63.7,-44.3 70,-40.5
  rectangle net SENSE.SENS_25_P: 63.875,-27.9 70,-21.6
  rectangle net SENSE.SENS_33_P: 39.8,-40 48.7,-36.85
  rectangle net NetC48_1: 39.8,-36.625 46.834,-32.6
  rectangle net NetC47_1: 43.2,-28 46.9,-24.525
  rectangle net VDD: 62.2,-21.2 70,-18.45
  rectangle net AGND: 39.2,2.7 40.8,4.4
  rectangle net P10V: 56.2,12.6 59.9,14.8
  rectangle net GND: 40.6,7.9 41.9,9.5
  rectangle net AGND: 72.5,14.125 75.1,21.8
  rectangle net GND: -37.2,6.1 -35.8,7.7
  rectangle net AVCC1V8: -37.2,2.6 -35.8,4.6
  rectangle net AGND: 33.4,-2.7 39.4,-0.8
  rectangle net NetC25_2: -19.1,-10.1 -17,-7.9
  rectangle net NetC25_2: -22.5,-10.1 -17.7,-8.5
  rectangle net VCC1V8: -16.453,-10.1 -14.5,-7.9
  rectangle net GND: -21.2,-6.2 -19.8,-3.6
  rectangle net GND: -23.4,-7.3 -19.8,-5.7
  rectangle net XADCGND: -39,-9.5 -38,-7.8
  rectangle: -40.5,-9.5 -39.5,-7.8
  rectangle net VCC2: -42,-9.5 -41,-7.8
  rectangle net AGND: 56.3,3.2 59.2,4.6
  rectangle net AGND: 57.8,3.2 60.3,5.1
  rectangle net AGND: 57.8,15.5 59.2,17.4
  rectangle net AGND: 62.3,15.2 64.3,16.8
  rectangle net AGND: 62.4,17.3 64.3,18.7
  rectangle net GND: 39.7,49 41.6,50.4
  rectangle net AGND: 62.2,-6.5 65.7,-4.9
  rectangle net AGND: 44.4,-10.7 45.6,-7.3
  rectangle net NetC35_2: 42.4,43.1 43.8,50.5
  rectangle net GND: 44.3,47.2 46.2,48.8
  rectangle net GND: 42.3,38.7 43.8,42.3
  rectangle net XADCGND: -32,-7 -30.3,-6
  rectangle net VCC: -29.4,3.6 -27.2,5.4
  rectangle net VCC2: -35.4,3.6 -30.6,5.4
  rectangle net VCC2: -50.1,3.9 -48.4,5.1
  rectangle net XADCGND: -52.4,3.9 -50.7,5.1
  rectangle net GND: 68.7,30.2 70.7,31.8
  rectangle net GND: 68.7,25.3 70.6,26.7
  rectangle net VCC: -44.2,25.9 -42.8,28.8
  rectangle net VCC: -51.2,25.9 -49.8,28.8
  rectangle net GND: -44.2,22.2 -42.8,25.1
  rectangle net GND: -51.3,22.7 -49.8,25.1
  rectangle net VCC: -30.4,22.7 -28.8,25.1
  rectangle net GND: -30.3,25.9 -28.8,28.8
  rectangle net BGND: -42.2,-36.2 -40.8,-33.9
  rectangle net VREF2V5: -43.8,-29.1 -42.4,-27.4
  rectangle net VREF2V5: -43.8,-33.3 -40.8,-31.2
  rectangle net N5V: -48.5,-28.6 -46.4,-27.2
  rectangle net BGND: -58.1,-26.8 -56.7,-24.6
  rectangle net BGND: -60.2,-26.8 -58.8,-24.6
  rectangle net BGND: -52.1,-34.3 -49.1,-32.8
  rectangle net P5V: -54.7,-34.2 -52.9,-32.8
  rectangle net BGND: -41.7,-26.6 -40.3,-24.8
  rectangle net BGND: -43.8,-26.6 -42.4,-24.8
  rectangle net BGND: -45.8,-26.6 -44.4,-24.8
  rectangle net BGND: -47.8,-26.6 -46.4,-24.8
  rectangle net VREF2V5: -52.2,-36.8 -49.1,-35.1
  rectangle net BGND: -48.2,-41.7 -46.8,-39.9
  rectangle net P5V: -42.5,-39.7 -41.1,-37.9
  rectangle net BGND: -45.7,-37.2 -40.8,-35.8
  rectangle net N5V: -47.8,-37.2 -46.4,-35.2
  rectangle net P5V: -58.2,-41.8 -56.8,-39.7
  rectangle net BGND: -62.7,-41.3 -58.9,-39.7
  rectangle net VREF2V5: -39.8,-43.2 -37.9,-41.8
  rectangle net BGND: -37.1,-43.2 -35.228,-41.8
  rectangle net GND: 20.1,-37.9 21.9,-35.6
  rectangle net GND: 28.3,-38.1 29.7,-36.3
  rectangle net 12V: 28.3,-40.7 29.7,-38.9
  rectangle net VDD: 18.8,23.2 20.5,25.2
  region: -6.4,-41.5
Int6 (Sign):
  rectangle net BUS12V: -36.3,-53 -33.5,-51
Bottom Layer:
  rectangle net BGND: -42.1,-35.5 -39.6,-33.1
  rectangle net VCC: 58.6,-24.8 59.4,-23.3
  rectangle net GND: 83.9,30.3 85.2,32.5
  rectangle net GND: 83.9,24.6 85.1,26.7
  rectangle net GND: 17.4,-17.8 18.6,-16.7
  rectangle net GND: 58.15,-28.2 59,-27.54
  rectangle net GND: -26.5,-5 -25.3,-3.9
  rectangle net GND: 7.8,12 9.2,17.9
  rectangle net VDD: 9.6,12 10.7,19.1
  rectangle net GND: 11.4,12 12.5,19
  rectangle net VDD: 13,12 14.2,19
  rectangle net VDD: 14.6,14.2 15.7,16
  rectangle net GND: 19.2,14.2 20.4,15.9
  rectangle net GND: -9.3,12.2 -7.7,19.2
  rectangle net VDD: -10.7,12.2 -9.6,19.2
  rectangle net GND: -12.5,12.2 -11.4,19.2
  rectangle net VDD: -14.2,12.2 -13.1,19.2
  rectangle net VDD: -15.9,16.2 -14.6,18.3
  rectangle net VDD: -15.7,13.2 -14.6,14.8
  rectangle net GND: -20.5,13.2 -19.2,14.8
  rectangle net GND: -20.5,16.2 -19.4,18.3
  rectangle net GND: 17.5,-14.6 18.7,-13.5
  rectangle net VCCINT: 14.7,-17.7 15.8,-16.6
  rectangle net VCCINT: 14.7,-14.4 16,-13.3
  rectangle net VREG: -54.3,-8.9 -53.5,-7.8
  rectangle net GND: 47.3,-26.7 48.7,-26.3
  rectangle net GND: 47.8,-26.7 48.2,-25.7
  rectangle net GND: 47.753,-25.75 48.3,-25.713
  rectangle net GND: 53.3,-24.2 53.7,-23.2
  rectangle net VCCINT: 49.1,-24.7 49.5,-23.4
  rectangle net GND: 50.1,-24.7 50.5,-23.2
  rectangle net GND: 57,-24.8 57.7,-23.3
  rectangle net GND: 12,2.5 19.1,3.7
  rectangle net VCC1V8: 12,-0.7 19.1,0.5
  rectangle net GND: -14.6,-1.4 -13.3,-0.3
  rectangle net XADC.XADC_REF_P: -29.35,0.6 -28.3,2.2
  rectangle net P10V: 39.2,13.5 56.9,15
  rectangle net P10V: 36.7,8.4 38.3,10.3
  rectangle net VCC: 25.8,7.637 29.3,8.3
  rectangle net GND: 21.8,2.5 27.2,4
  rectangle net VCC: 21.8,5.7 27.2,8.3
  rectangle net AVCC1V8: -37.2,2.6 -34.7,4.4
  rectangle net XADCGND: -31.3,-5 -28.7,-1.4
  rectangle net XADCGND: -36.1,-1.9 -34.7,-0.3
  rectangle net XADCGND: -36.1,-2.5 -32.4,-1.4
  rectangle net XADCVCC: -33,1 -32,2.275
  rectangle net XADCVCC: -36.1,1.35 -32,1.898
  rectangle net AVTT: -17.057,-3 -15.9,-0.017
  rectangle net GND: -17.9,-5.3 -15.8,-3.7
  rectangle net AVTT: -24.8,-3.8 -22.7,-2.9
  rectangle net XADCVCC: -31.7,0.6 -30.7,2.2
  rectangle net XADCGND: -33,-2.5 -27,-0.2
  rectangle net VCC2: -40.5,-3.8 -38.9,-2.7
  rectangle net XADCGND: -41.1,-5.5 -39.5,-4.4
  rectangle net AGND: 39.2,2.6 40.8,4.4
  rectangle net AGND: 35.4,5.6 36,8
  rectangle net GND: 44.5,49 46.3,50.4
  rectangle net GND: 44.5,35.3 46.3,36.7
  rectangle net GND: 40.7,37.3 42.6,38.7
  rectangle net GND: 20.2,-36.2 21.8,-33.9
  rectangle net XADCGND: -53,0.802 -43.035,1.9
  rectangle net XADCGND: -45.5,0.8 -43,3
  rectangle net VCC: 52.6,-9.9 54.9,-8.1
  rectangle net VCC: 48.9,47.02 51.8,48.5
  rectangle net VCC: 48.9,37.2 51.8,38.6
  rectangle net BGND: -58.1,-20.4 -56.3,-19
  rectangle net BGND: -35.6,-34.9 -34.2,-33.1
  rectangle net N12V: -35.6,-37.6 -34.2,-35.7
  rectangle net P12V: -56.9,-23 -55.7,-20.8
  rectangle net P12V: -61.3,-23 -60.1,-20.8
  rectangle net P5V: -53.7,-26.9 -52.1,-24.5
  rectangle net BGND: -50.9,-26.9 -49.3,-24.5
  rectangle net BGND: -54.1,-30.2 -52.3,-28.8
  rectangle net BGND: -60.2,-25.2 -58.8,-24.6
  rectangle net BGND: -47.8,-25.4 -46.4,-24.8
  rectangle net BGND: -47.8,-30.2 -46.9,-24.8
  rectangle net VREF2V5: -45.6,-30.2 -42.4,-28.5
  rectangle net P5V: -41.1,-29.6 -40.1,-27.4
  rectangle net BGND: -41.7,-25.6 -39.3,-24.8
  rectangle net BGND: -43.9,-38.4 -42.5,-35.9
  rectangle net P5V: -43.9,-40.4 -41.2,-39.2
  rectangle net N5V: -39.6,-32.7 -37.8,-31.3
  rectangle net N5V: -41.5,-37.6 -38,-35.9
  region net VCC1V8: 7,-19 7,-15.7 4.9,-15.7 4.9,-19
  rectangle net AVCC: -5.6,-21.5 -4.7,-19.8
  region net GND: -1.6,-21.4 -1.6,-19.5 -2.8,-19.5 -2.8,-21.4
  region net GND: -7,-17.3 -7,-15.6 -9.7,-15.6 -9.7,-17.3
  region net GND: -8,-13.8 -9.7,-13.8 -9.7,-17.3 -8,-17.3
  region net AVCC: -5.7,-15.4 -5.7,-13.8 -7.7,-13.8 -7.7,-15.4
  region net GND: 7.3,-14.9 7.3,-12.1 4.5,-12.1 4.5,-14.9
  rectangle net GND: -23.4,-5.8 -21.6,-4.7
  rectangle net GND: -23.4,-7.1 -22.6,-4.7
  region: -54.3,-8.9
  region: -54.3,-8.9
  region net SENS15: -6.4,-41.5 -6.4,-39.9 -5.3,-39.9 -5.3,-41.5
Int1 (GND) (plane layer: these items are gaps in the copper):
  lines w0.5: -5,-46.2 -5,-36.5 -3.5,-35 ; 20,52 20,47 24.5,42.5 61.6,42.5 79.5,24.6 79.5,6.5 79.5,5 68,-6.5 67.5,-7 64,-10.5 60.2,-10.5 30.5,-10.5 29,-12 29,-14.5 32.5,-18 39.5,-25 39.5,-33.5 -2,-33.5 -3.5,-35 ; -40,-12.5 -39,-12.5 -36,-9.5 -36,-6.5 -36,0 ; -40,-12.5 -40,-12.5 ; -40,-12.5 -58,-12.5 -60.9,-9.6 -60.9,1.6 -56,6.5 -47.5,6.5 -41.2,6.5 -34,6.5 -33,5.5 -33,4 ; -36,0 -36,1 -33,4 ; -36,0 -20.5,0 -20.5,4 -31.5,4 -33,4 ; -3.5,-35 -3.5,-35 ; -55,-44 -55,-25 -38,-25 -38,-44 -55,-44 ; -17,-10 -17,-1.5 -13,2.5 20,2.5 20,-2 20,-3.5 6.5,-17 4.5,-17 0.5,-13 0.5,-1.5 -11,-1.5 -13.5,-4 -13.5,-9 -14.5,-10 -17,-10 ; 72.5,-36.55 80.05,-44.1 82,-44.1 82.9,-44.1 84,-43 84,-42.5 84,-33 76.5,-25.5 74,-25.5 72.5,-27 72.5,-36.55
Int4 (PWR) (plane layer: these items are gaps in the copper):
  lines w0.5: -22.5,-0.5 -25,-0.5 ; -8.5,-8.5 -8.5,-21 ; -4.5,-6.5 -4.5,-4.5 -4.5,13.5 ; -4.5,-5.5 -4.5,-21 ; 5.499,-1.5 10.3,-1.5 16.5,-1.5 ; 60.6,-40 60.6,-40.1 64.3,-43.8 64.9,-43.8 ; 61,-40.5 50.5,-30 41,-30 38,-30 29,-21 20.5,-21 -4.5,-21 ; 64.5,-43.8 65.7,-43.8 66.6,-42.9 ; 66,-43.5 66.6,-42.9 ; 96,-33 96,-22.8 ; 96,-8.6 96,31.5 ; -25,-0.5 -25,13.5 -4.5,13.5 ; -25,-0.5 -19.625,-0.5 -10.5,-0.5 -9.5,-0.5 -9.5,-3.5 -8.5,-3.5 -8.5,-21 ; -25,-0.5 -25,-21 -8.5,-21 ; -8.5,-21 -4.5,-21 ; -4.5,13.5 11.5,13.5 25,0 ; -4.5,13.5 -4.5,1 -4.5,-0.5 -3.5,-0.5 -0.5,-0.5 1.5,-0.5 2.5,-0.5 2.5,-1.5 3.5,-1.5 16.5,-1.5 ; 16.5,-1.5 17,-1.5 20.5,-5 35,-19.5 35,-21.3 40.5,-26.8 51.8,-26.8 65.8,-40.8 66.6,-41.6 66.6,-41.7 66.6,-42.9 ; 25,0 25,0 ; 25,0 34.6,-9.6 42.8,-17.8 42.8,-26.8 ; 42.8,-26.8 42.8,-26.8 ; 36.5,0.8 36.9,0.4 38.4,0.4 39.7,0.4 40.7,1.4 40.7,1.8 38.5,4 38.5,10.2 38.1,10.6 36.9,10.6 36.5,10.2 36.5,0.8 ; 71.5,26.5 71.5,26.5
Int5 (GND) (plane layer: these items are gaps in the copper):
  lines w0.5: -27.8,-30.4 0.4,-30.4 2.5,-32.5 2.5,-33.2 ; -27.7,-30.4 -30.1,-30.4 -30.7,-29.8 ; -16.7,-46.25 -12,-46.25 ; 2.5,-33.074 2.5,-36.6 ; 3.9,-42.5 3.7,-42.5 2.9,-42.5 -0.5,-39.1 -0.5,-34 -1.7,-32.8 -28.9,-32.8 -29.5,-32.8 -30.5,-33.8 -30.5,-35.2 -29.5,-36.2 -27.6,-36.2 -26.5,-37.3 -26.5,-39.9 -27.6,-41 -29.6,-41 -30.5,-41.9 -30.5,-42.7 -31.2,-43.4 -32.5,-43.4 -38.3,-43.4 -39.975,-43.4 -42.9,-43.4 -44.3,-42 -61.3,-42 -61.7,-42 -61.7,-24.9 -61.7,-18.8 -54.6,-18.8 -41.7,-18.8 -30.7,-29.8 ; 4,-42.5 5.4,-42.5 9.4,-38.5 10.9,-38.5 11.7,-39.3 11.7,-39.7 11.7,-44.1 13.6,-44.1 14.3,-44.1 14.3,-37.7 11.3,-34.7 9.8,-34.7 9.5,-34.7 5.2,-39 3.5,-39 2.5,-38 ; -30.7,-29.8 -30.7,-29.8 ; 2.5,-38 2.5,-36.6 ; 2.5,-38 2.5,-36.6 ; -60.9,-13.6 -60.9,1.6 -56,6.5 -36,6.5 -33.5,6.5 -30.8,6.5 -29.8,5.5 -27.5,3.2 -24.311,3.2 -20.6,3.2 -20.6,0.8 -23.1,0.8 -23.1,-3.2 -23.8,-3.9 -26.3,-3.9 -27.9,-5.5 -29.5,-5.5 -40.1,-16.1 -58.4,-16.1 -60.9,-13.6 ; -35.4,-25.1 -35.4,-25.1 ; 32,-2.5 33.5,-4 39.5,-4 42.5,-7 42.5,-12 46,-15.5 64,-15.5 78.5,-1 81,1.5 81,3 81,14.5 75.5,20 53.5,20 50.5,17 50.5,10 48.5,8 34.5,8 32,5.5 32,-2.5
Int8 (GND) (plane layer: these items are gaps in the copper):
  lines w0.5: -38.9,-46.25 -38.648,-45.998 -36.505,-45.998 -34,-43.493 -34,-26.5 -41.6,-18.9 -60.4,-18.9 -67,-25.5 -67,-46.003 -37.571,-46.003 ; 46.6,-46.3 96,-46.3 96,-34 96,-24.5

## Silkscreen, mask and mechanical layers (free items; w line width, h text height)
Top Overlay:
  rectangle: -81.3,42 -64,47.9
  text "D2000329" at -81.3,38.5 h4.57
  text "rev 0 / serial" at -81.5,31 h3.05
PCI-SIG Outline:
  lines w0.1: -82,-54.5 -82,52.15 96,52.15 96,-46.25 -16.7,-46.25 -16.7,-58.5 -17.2,-59 -23.4,-59 -23.9,-58.5 -23.9,-51.55 ccw(c-24.85,-51.55) -25.8,-51.55 -25.8,-58.5 -26.3,-59 -36.5,-59 -37,-58.5 -37,-48.075 ccw(c-38.825,-48.075) -40.65,-48.075 -40.65,-54.5 -48.65,-54.5 -48.65,-46.25 -67,-46.25 -67,-54.5 -82,-54.5
Mechanical7:
  lines w0.1: -82,-45.25 -82,-54.5 -67,-54.5 -67,-46.25 -48.65,-46.25 -48.65,-51.05 -40.65,-51.05 -40.65,-48.075 cw(c-38.825,-48.075) -37,-48.075 -37,-45.25 ; -81.75,-46.5 -36.75,-46.5

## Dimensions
-82,-59 to -82,52.15 on PCI-SIG Dimensions
-82,-54.5 to -82,52.15 on PCI-SIG Dimensions
-82,52.15 to 96,52.5 on PCI-SIG Dimensions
